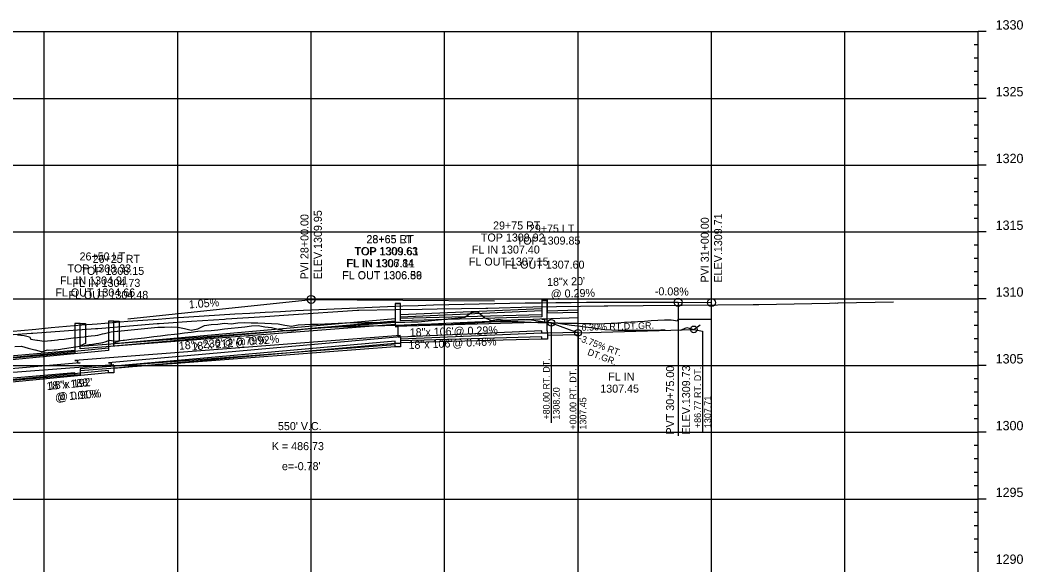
# Model space of a CAD drawing. Extents: x 670877 to 686811, y 705985 to 708501.
# Drawn here: x 686059 to 686811, y 708094 to 708501 of the extents above; entities that cross this region are included whole.
import ezdxf

# ---------------------------------------------------------------- set-up
doc = ezdxf.new("R2010")
doc.units = 0
for name, color, linetype in [('30', 7, 'Continuous'), ('37', 7, 'Continuous'), ('DRAINAGE_HGL LEFT', 7, 'Continuous'), ('DRAINAGE_HGL RIGHT', 7, 'Continuous'), ('Profile Drainage Annot Left', 7, 'Continuous'), ('Profile Drainage Annot Right', 7, 'Continuous'), ('R_Drainage Extensions_LEFT', 7, 'Continuous'), ('R_Drainage Extensions_RIGHT', 7, 'Continuous'), ('R_Drainage LEFT', 7, 'Continuous'), ('R_Drainage RIGHT', 7, 'Continuous'), ('R_Exist Surface', 7, 'Continuous'), ('R_Profile Work Left', 7, 'Continuous'), ('R_Proposed Const Limits', 7, 'Continuous'), ('R_Vert Alg', 7, 'Continuous'), ('R_Vert Alg Annot', 7, 'Continuous'), ('R_Vert Alg RT DT', 7, 'Continuous'), ('R_Vert Alg RT DT Annot', 7, 'Continuous')]:
    doc.layers.add(name, color=color, linetype=linetype)

msp = doc.modelspace()

# ---------------------------------------------------------------- linework, layer by layer
at = {"layer": '37'}
for p, q in [((684477.28, 708492.85), (686777.28, 708492.85)), ((686077.28, 707892.85), (686077.28, 708492.85)), ((686177.28, 707892.85), (686177.28, 708492.85)), ((686277.28, 707892.85), (686277.28, 708492.85)), ((686377.28, 707892.85), (686377.28, 708492.85)), ((686477.28, 707892.85), (686477.28, 708492.85)), ((686577.28, 707892.85), (686577.28, 708492.85)), ((686677.28, 707892.85), (686677.28, 708492.85)), ((686777.28, 707892.85), (686777.28, 708492.85)), ((686783.28, 708492.85), (686777.28, 708492.85)), ((686777.28, 708482.85), (686774.28, 708482.85)), ((686777.28, 708472.85), (686774.28, 708472.85)), ((686777.28, 708462.85), (686774.28, 708462.85)), ((686777.28, 708452.85), (686774.28, 708452.85)), ((684477.28, 708442.85), (686777.28, 708442.85)), ((686783.28, 708442.85), (686777.28, 708442.85)), ((686777.28, 708432.85), (686774.28, 708432.85)), ((686777.28, 708422.85), (686774.28, 708422.85)), ((686777.28, 708412.85), (686774.28, 708412.85)), ((686777.28, 708402.85), (686774.28, 708402.85)), ((684477.28, 708392.85), (686777.28, 708392.85)), ((686783.28, 708392.85), (686777.28, 708392.85)), ((686777.28, 708382.85), (686774.28, 708382.85)), ((686777.28, 708372.85), (686774.28, 708372.85)), ((686777.28, 708362.85), (686774.28, 708362.85)), ((686777.28, 708352.85), (686774.28, 708352.85)), ((684477.28, 708342.85), (686777.28, 708342.85)), ((686783.28, 708342.85), (686777.28, 708342.85)), ((686777.28, 708332.85), (686774.28, 708332.85)), ((686777.28, 708322.85), (686774.28, 708322.85)), ((686777.28, 708312.85), (686774.28, 708312.85)), ((686777.28, 708302.85), (686774.28, 708302.85)), ((684477.28, 708292.85), (686777.28, 708292.85)), ((686783.28, 708292.85), (686777.28, 708292.85)), ((686777.28, 708282.85), (686774.28, 708282.85)), ((686777.28, 708272.85), (686774.28, 708272.85)), ((686777.28, 708262.85), (686774.28, 708262.85)), ((686777.28, 708252.85), (686774.28, 708252.85)), ((684477.28, 708242.85), (686777.28, 708242.85)), ((686783.28, 708242.85), (686777.28, 708242.85)), ((686777.28, 708232.85), (686774.28, 708232.85)), ((686777.28, 708222.85), (686774.28, 708222.85)), ((686777.28, 708212.85), (686774.28, 708212.85)), ((686777.28, 708202.85), (686774.28, 708202.85)), ((684477.28, 708192.85), (686777.28, 708192.85)), ((686783.28, 708192.85), (686777.28, 708192.85)), ((686777.28, 708182.85), (686774.28, 708182.85)), ((686777.28, 708172.85), (686774.28, 708172.85)), ((686777.28, 708162.85), (686774.28, 708162.85)), ((686777.28, 708152.85), (686774.28, 708152.85)), ((684477.28, 708142.85), (686777.28, 708142.85)), ((686783.28, 708142.85), (686777.28, 708142.85)), ((686777.28, 708132.85), (686774.28, 708132.85)), ((686777.28, 708122.85), (686774.28, 708122.85)), ((686777.28, 708112.85), (686774.28, 708112.85)), ((686777.28, 708102.85), (686774.28, 708102.85))]:
    msp.add_line(p, q, dxfattribs=at)
at = {"layer": 'DRAINAGE_HGL LEFT'}
msp.add_lwpolyline([(686452.28, 708277.68), (686454.28, 708277.68), (686454.28, 708277.68), (686454.28, 708277.68), (686340.29, 708272.6), (686342.29, 708272.6), (686342.29, 708264.29), (686344.29, 708264.29), (686125.29, 708244.79), (686127.29, 708244.79), (686127.29, 708243.32), (686129.3, 708243.32), (685935.28, 708228.55), (685937.28, 708228.55), (685937.28, 708228.55), (685939.3, 708228.55), (685859.24, 708224.45), (685857.24, 708224.45), (685857.24, 708222.25), (685855.24, 708222.25), (685780.74, 708218.25), (685782.77, 708218.25)], dxfattribs=at)
at = {"layer": 'DRAINAGE_HGL RIGHT'}
msp.add_lwpolyline([(686477.28, 708278.42), (686450.04, 708277.56), (686452.28, 708277.56), (686452.28, 708275.36), (686454.28, 708275.36), (686340.29, 708272.17), (686342.29, 708272.17), (686342.29, 708265.24), (686344.29, 708265.24), (686100.28, 708246.64), (686102.28, 708246.64), (686102.28, 708244.78), (686104.28, 708244.78), (685905.28, 708227.58), (685907.28, 708227.58), (685907.28, 708225.28), (685909.33, 708225.28), (685800.25, 708213.48), (685802.28, 708213.48)], dxfattribs=at)
at = {"layer": 'R_Drainage Extensions_LEFT'}
msp.add_lwpolyline([(686129.29, 708276.15), (686133.29, 708276.15), (686133.29, 708261.15), (686129.29, 708259.48), (686129.29, 708276.15)], dxfattribs=at)
at = {"layer": 'R_Drainage Extensions_RIGHT'}
msp.add_lwpolyline([(686104.28, 708274.35), (686108.28, 708274.35), (686108.28, 708259.35), (686104.28, 708257.68), (686104.28, 708274.35)], dxfattribs=at)
at = {"layer": 'R_Drainage LEFT'}
for points in [[(686344.29, 708288.95), (686340.29, 708288.95)], [(686340.29, 708288.95), (686340.29, 708276.09)], [(686344.29, 708279.12), (686344.29, 708288.95)], [(686454.28, 708291.35), (686450.28, 708291.35)], [(686450.28, 708291.35), (686450.28, 708283.68)], [(686454.28, 708268.85), (686454.28, 708291.35)], [(686450.28, 708285.34), (686344.29, 708280.79)], [(686450.28, 708283.68), (686344.29, 708279.12)], [(686129.29, 708276.15), (686125.28, 708276.15)], [(686125.28, 708276.15), (686125.28, 708254.06)], [(686340.29, 708277.76), (686129.29, 708258.97)], [(686129.29, 708257.3), (686129.29, 708276.15)], [(686340.29, 708276.09), (686129.29, 708257.3)], [(686450.28, 708268.68), (686344.29, 708264.12)], [(686450.28, 708267.01), (686344.29, 708262.45)], [(686450.28, 708267.01), (686450.28, 708268.68)], [(686454.28, 708267.01), (686450.28, 708267.01)], [(686454.28, 708268.85), (686454.28, 708267.01)], [(686340.29, 708261.09), (686129.29, 708242.3)], [(686340.29, 708259.42), (686129.29, 708240.64)], [(686340.29, 708259.42), (686340.29, 708261.09)], [(686344.29, 708259.42), (686340.29, 708259.42)], [(686344.29, 708264.12), (686344.29, 708259.42)], [(686125.28, 708255.73), (685939.29, 708237.7)], [(686125.28, 708254.06), (685939.29, 708236.04)], [(686125.28, 708239.06), (685939.29, 708221.04)], [(686125.28, 708237.39), (685939.29, 708219.37)], [(686125.28, 708237.39), (686125.28, 708239.06)], [(686129.29, 708237.39), (686125.28, 708237.39)], [(686129.29, 708242.3), (686129.29, 708237.39)]]:
    msp.add_lwpolyline(points, dxfattribs=at)
at = {"layer": 'R_Drainage RIGHT'}
for points in [[(686344.29, 708289.15), (686340.29, 708289.15)], [(686340.29, 708289.15), (686340.29, 708273.44)], [(686344.29, 708276.38), (686344.29, 708289.15)], [(686454.39, 708292.05), (686450.16, 708292.05)], [(686450.16, 708292.05), (686450.16, 708279.24)], [(686454.39, 708281.93), (686454.39, 708292.05)], [(686450.16, 708280.9), (686344.29, 708278.05)], [(686477.28, 708284.21), (686454.39, 708283.59)], [(686477.28, 708282.55), (686454.39, 708281.93)], [(686104.28, 708274.35), (686100.28, 708274.35)], [(686100.28, 708274.35), (686100.28, 708252.3)], [(686340.29, 708275.11), (686104.28, 708257.12)], [(686104.28, 708255.45), (686104.28, 708274.35)], [(686340.29, 708273.44), (686104.28, 708255.45)], [(686450.16, 708279.24), (686344.29, 708276.38)], [(686477.28, 708267.55), (686454.39, 708266.93)], [(686454.39, 708266.93), (686454.39, 708262.57)], [(686477.28, 708265.88), (686454.39, 708265.26)], [(686340.29, 708258.44), (686104.28, 708240.45)], [(686340.29, 708256.78), (686340.29, 708258.44)], [(686450.16, 708264.24), (686344.29, 708261.38)], [(686450.16, 708262.57), (686344.29, 708259.72)], [(686344.29, 708261.38), (686344.29, 708256.78)], [(686450.16, 708262.57), (686450.16, 708264.24)], [(686454.39, 708262.57), (686450.16, 708262.57)], [(686100.28, 708253.97), (685909.3, 708237.46)], [(686100.28, 708252.3), (685909.3, 708235.8)], [(686340.29, 708256.78), (686104.28, 708238.79)], [(686344.29, 708256.78), (686340.29, 708256.78)], [(686100.28, 708237.3), (685909.3, 708220.8)], [(686100.28, 708235.64), (685909.3, 708219.13)], [(686100.28, 708235.64), (686100.28, 708237.3)], [(686104.28, 708235.64), (686100.28, 708235.64)], [(686104.28, 708240.45), (686104.28, 708235.64)]]:
    msp.add_lwpolyline(points, dxfattribs=at)
at = {"layer": 'R_Exist Surface'}
msp.add_lwpolyline([(686030.1, 708264.31), (686067.48, 708267.1), (686068.62, 708267.17), (686115.63, 708270.52), (686117.49, 708270.65), (686161.8, 708274.28), (686163.28, 708274.37), (686187.67, 708276.07), (686212.34, 708277.63), (686213.68, 708277.76), (686242.8, 708279.63), (686260.23, 708280.66), (686312.09, 708284.35), (686312.9, 708284.38), (686340.19, 708284.8), (686360.44, 708285.01), (686371.65, 708285.24), (686408.11, 708285.73), (686409.72, 708285.77), (686443.39, 708286.72), (686443.53, 708286.73), (686496.92, 708287.44), (686499.62, 708287.49), (686552.62, 708287.98), (686555.28, 708287.99), (686608.5, 708288.53), (686612.92, 708288.58), (686665.84, 708289.62), (686670.56, 708289.72), (686671.73, 708289.54), (686672.16, 708289.7), (686713.62, 708290.61)], dxfattribs=at)
at = {"layer": 'R_Profile Work Left'}
msp.add_lwpolyline([(686055.07, 708256.97), (686060.08, 708257.29), (686065.14, 708255.92), (686070.18, 708254.56), (686070.36, 708254.51), (686075.03, 708253.25), (686075.48, 708253.13), (686079.79, 708254.6), (686080.53, 708254.31), (686084.6, 708254.49), (686085.6, 708254.62), (686089.39, 708255.11), (686090.67, 708255.28), (686094.17, 708255.76), (686095.74, 708256.02), (686098.95, 708256.55), (686100.81, 708256.85), (686103.74, 708257.32), (686105.89, 708257.67), (686108.52, 708258.1), (686110.96, 708258.49), (686113.31, 708258.86), (686116.05, 708259.3), (686118.1, 708259.63), (686121.13, 708260.11), (686122.88, 708260.64), (686126.21, 708261.76), (686127.68, 708261.55), (686131.31, 708261.1), (686132.47, 708261.25), (686136.4, 708261.79), (686137.28, 708261.92), (686142.28, 708262.5), (686147.28, 708263.09), (686152.28, 708263.68), (686159.32, 708264.51), (686164.43, 708265.12), (686169.72, 708265.74), (686174.83, 708266.35), (686177.46, 708266.66), (686182.46, 708267.26), (686187.46, 708267.85), (686192.46, 708268.45), (686197.46, 708268.92), (686202.46, 708269.08), (686207.46, 708269.63), (686212.45, 708270.19), (686217.45, 708270.75), (686222.45, 708271.3), (686227.45, 708271.86), (686232.45, 708272.42), (686237.45, 708272.9), (686242.45, 708271.9), (686247.46, 708271.29), (686252.46, 708270.14), (686257.47, 708268.98), (686262.47, 708268.87), (686267.47, 708269.5), (686272.47, 708270.18), (686277.47, 708270.87), (686282.47, 708271.35), (686287.47, 708271.51), (686292.47, 708271.67), (686297.47, 708271.83), (686302.47, 708271.99), (686307.47, 708272.15), (686312.47, 708272.3), (686317.47, 708272.46), (686322.47, 708272.6), (686327.47, 708272.71), (686332.47, 708272.81), (686337.47, 708272.92), (686342.47, 708273.11), (686343.47, 708273.14), (686347.11, 708273.29), (686352.12, 708273.49), (686357.12, 708273.7), (686362.11, 708273.68), (686367.11, 708273.66), (686372.11, 708273.64), (686377.11, 708273.62), (686382.11, 708273.87), (686387.11, 708274.17), (686392.11, 708274.47), (686397.12, 708274.75), (686400.12, 708274.91), (686402.12, 708275.02), (686407.12, 708275.3), (686412.12, 708275.57), (686417.12, 708275.81), (686422.12, 708275.77), (686427.12, 708275.73), (686432.12, 708275.7), (686437.12, 708275.57), (686442.11, 708275.26), (686447.11, 708275.13), (686452.11, 708275.01), (686457.11, 708274.9), (686462.11, 708274.78), (686467.11, 708274.66), (686472.11, 708274.55), (686477.11, 708274.47), (686482.11, 708274.39), (686487.11, 708274.32), (686492.11, 708274.02), (686497.11, 708274.28), (686502.11, 708274.59), (686507.11, 708274.9), (686512.11, 708275.21), (686517.11, 708275.52), (686522.12, 708275.84), (686527.12, 708276.15), (686532.12, 708276.46), (686537.12, 708276.78), (686542.12, 708277.09), (686547.12, 708277.08), (686552.12, 708276.32), (686552.28, 708277.47), (686557.28, 708277.47), (686562.28, 708277.47), (686567.28, 708277.47), (686572.28, 708277.47), (686577.28, 708277.46)], dxfattribs=at)
at = {"layer": 'R_Proposed Const Limits'}
for points in [[(686057.28, 708265.81), (686062.28, 708265.27), (686066.3, 708264.22), (686067.28, 708262.62), (686071.76, 708261.84), (686072.28, 708261.72), (686077.21, 708260.97), (686077.28, 708260.98), (686082.28, 708261.54), (686082.67, 708261.59), (686087.28, 708262.11), (686088.14, 708262.21), (686092.28, 708262.68), (686093.61, 708262.83), (686097.28, 708263.24), (686099.08, 708263.45), (686102.28, 708263.81), (686104.55, 708264.07), (686107.28, 708264.38), (686110.03, 708264.69), (686112.28, 708264.94), (686115.51, 708265.31), (686117.28, 708265.51), (686120.99, 708266.44), (686122.28, 708266.77), (686126.47, 708267.83), (686127.28, 708268.04), (686131.95, 708268.64), (686132.28, 708268.66), (686137.28, 708269.02), (686137.43, 708269.03), (686142.28, 708269.48), (686147.28, 708269.99), (686147.31, 708269.99), (686152.28, 708270.49), (686157.28, 708271), (686162.28, 708271.44), (686167.43, 708271.63), (686172.43, 708271.76), (686177.43, 708271.53), (686182.44, 708270.51), (686187.44, 708269.31), (686192.44, 708270.19), (686197.43, 708272.8), (686202.43, 708273.55), (686207.43, 708273.87), (686212.43, 708274.53), (686217.43, 708273.96), (686222.43, 708274.85), (686227.43, 708275.12), (686232.43, 708274.9), (686237.43, 708274.68), (686242.44, 708274.46), (686247.44, 708274.24), (686252.44, 708274.02), (686257.44, 708273.13), (686262.45, 708272.2), (686267.45, 708273.21), (686272.45, 708273.44), (686277.45, 708273.68), (686282.45, 708273.91), (686287.45, 708274.14), (686292.45, 708274.38), (686297.45, 708274.61), (686302.45, 708274.84), (686307.45, 708275.07), (686312.45, 708274.89), (686317.45, 708274.97), (686322.45, 708275.04), (686327.45, 708275.1), (686332.45, 708275.16), (686337.45, 708275.23), (686342.45, 708275.29), (686343.45, 708275.3), (686347.45, 708275.35), (686352.45, 708275.42), (686357.45, 708275.58), (686362.45, 708276.06), (686367.45, 708276.57), (686372.45, 708277.08), (686377.45, 708277.59), (686382.44, 708278.1), (686387.44, 708278.61), (686392.44, 708279.12), (686397.43, 708282.41), (686400.43, 708282.91), (686402.43, 708282.77), (686407.45, 708278.48), (686412.45, 708276.52), (686417.45, 708277.56), (686422.45, 708276.86), (686427.45, 708277.1), (686432.45, 708277.33), (686437.45, 708277.28), (686442.45, 708277.12), (686447.46, 708276.27), (686452.46, 708275.42), (686457.46, 708274.95), (686462.46, 708274.43), (686467.47, 708273.79), (686472.47, 708273.14), (686477.47, 708272.49), (686482.47, 708271.84), (686487.48, 708271.19), (686492.48, 708270.55), (686497.48, 708269.82), (686502.48, 708269.43), (686507.48, 708269.42), (686512.48, 708269.4), (686517.48, 708269.39), (686522.48, 708269.37), (686527.48, 708269.35), (686532.48, 708269.34), (686537.48, 708269.32), (686542.48, 708269.31), (686539.29, 708269.33)], [(686554.03, 708269.38), (686558.87, 708271.21), (686564.05, 708269.91), (686568.72, 708273.34)]]:
    msp.add_lwpolyline(points, dxfattribs=at)
at = {"layer": 'R_Vert Alg'}
for p, q in [((686139.78, 708277.89), (686277.28, 708292.35)), ((686277.28, 708292.35), (686414.78, 708291.25)), ((686552.28, 708290.15), (686577.28, 708289.95))]:
    msp.add_line(p, q, dxfattribs=at)
msp.add_lwpolyline([(686048.11, 708268.03), (686059.57, 708269.12), (686071.03, 708270.17), (686082.49, 708271.2), (686093.94, 708272.2), (686105.4, 708273.18), (686116.86, 708274.13), (686128.32, 708275.05), (686139.78, 708275.94), (686151.24, 708276.81), (686162.69, 708277.65), (686174.15, 708278.46), (686185.61, 708279.25), (686197.07, 708280.01), (686208.53, 708280.74), (686219.99, 708281.45), (686231.44, 708282.13), (686242.9, 708282.78), (686254.36, 708283.4), (686265.82, 708284), (686288.74, 708285.11), (686300.19, 708285.63), (686311.65, 708286.12), (686323.11, 708286.58), (686334.57, 708287.01), (686346.03, 708287.42), (686357.49, 708287.8), (686368.94, 708288.16), (686380.4, 708288.48), (686391.86, 708288.78), (686403.32, 708289.06), (686414.78, 708289.3), (686426.24, 708289.52), (686437.69, 708289.71), (686449.15, 708289.88), (686460.61, 708290.02), (686472.07, 708290.13), (686483.53, 708290.21), (686494.99, 708290.27), (686506.44, 708290.3), (686517.9, 708290.3), (686529.36, 708290.28), (686540.82, 708290.23), (686552.28, 708290.15)], dxfattribs=at)
for centre in [(686277.28, 708292.35), (686552.28, 708290.15), (686577.28, 708289.95)]:
    msp.add_circle(centre, 3, dxfattribs=at)
at = {"layer": 'R_Vert Alg Annot'}
for p, q in [((686277.28, 708292.35), (686277.28, 708382.35)), ((686577.28, 708289.95), (686577.28, 708379.95)), ((686552.28, 708290.15), (686552.28, 708190.15))]:
    msp.add_line(p, q, dxfattribs=at)
at = {"layer": 'R_Vert Alg RT DT'}
for p, q in [((686457.28, 708274.85), (686477.28, 708267.35)), ((686477.28, 708267.35), (686564.04, 708269.91))]:
    msp.add_line(p, q, dxfattribs=at)
for centre in [(686457.28, 708274.85), (686564.04, 708269.91), (686477.28, 708267.35)]:
    msp.add_circle(centre, 2.5, dxfattribs=at)
at = {"layer": 'R_Vert Alg RT DT Annot'}
for p, q in [((686457.28, 708274.85), (686457.28, 708199.85)), ((686477.28, 708267.35), (686477.28, 708192.35))]:
    msp.add_line(p, q, dxfattribs=at)
msp.add_lwpolyline([(686564.04, 708269.91), (686570.7, 708268.51), (686570.7, 708193.51)], dxfattribs=at)

# ---------------------------------------------------------------- texts
at = {"layer": '30'}
for s, p in [('1330', (686790.28, 708494.35)), ('1325', (686790.28, 708444.35)), ('1320', (686790.28, 708394.35)), ('1315', (686790.28, 708344.35)), ('1310', (686790.28, 708294.35)), ('1305', (686790.28, 708244.35)), ('1300', (686790.28, 708194.35)), ('1295', (686790.28, 708144.35)), ('1290', (686790.28, 708094.35))]:
    msp.add_text(s, height=7, dxfattribs=at).set_placement(p)
at = {"layer": 'Profile Drainage Annot Left'}
for s, p in [('29+75 LT', (686440.45, 708342.36)), ('28+65 LT', (686318.71, 708334.31)), ('TOP 1309.85', (686431.34, 708333.36)), ('26+50 LT', (686103.71, 708321.51)), ('TOP 1309.61', (686310.04, 708325.31)), ('TOP 1308.33', (686094.6, 708312.51)), ('FL IN 1307.11', (686304.04, 708316.31)), ('FL OUT 1307.60', (686422.38, 708315.36)), ('FL OUT 1306.86', (686300.6, 708307.31)), ('FL IN 1304.91', (686089.04, 708303.51)), ('FL OUT 1304.66', (686085.6, 708294.51)), ('FL IN ', (686499.91, 708231.53)), ('1307.45', (686493.97, 708222.53))]:
    msp.add_text(s, height=6, dxfattribs=at).set_placement(p)
for s, rotation, p in [('18"x 212\'@ 0.92%', 5.08825, (686187.78, 708254.03)), ('18"x 106\'@ 0.46%', 2.46144, (686350.33, 708255.08)), ('18"x 188\'', 5.53462, (686079.17, 708224.33)), ('@ 1.01%', 5.53462, (686085.56, 708215.91))]:
    msp.add_text(s, height=6, rotation=rotation, dxfattribs=at).set_placement(p)
at = {"layer": 'Profile Drainage Annot Right'}
for s, p in [('29+75 RT', (686413.61, 708344.67)), ('28+65 RT', (686318.71, 708334.51)), ('TOP 1309.92', (686404.49, 708335.67)), (' FL IN 1307.40', (686395.53, 708326.67)), ('26+25 RT', (686113.5, 708319.71)), ('TOP 1309.63', (686309.6, 708325.51)), ('FL IN 1306.84', (686303.6, 708316.51)), ('FL OUT 1307.15', (686395.49, 708317.67)), ('TOP 1308.15', (686104.39, 708310.71)), ('FL OUT 1306.59', (686300.57, 708307.51)), ('FL IN 1304.73', (686098.39, 708301.71)), ('FL OUT 1304.48', (686095.4, 708292.71))]:
    msp.add_text(s, height=6, dxfattribs=at).set_placement(p)
for s, rotation, p in [('18"x 20\'', 1.55782, (686454.16, 708302.37)), ('@ 0.29%', 1.55782, (686456.95, 708293.45)), ('18"x 236\'@ 0.79%', 4.20867, (686178.29, 708254.58)), ('18"x 106\'@ 0.29%', 1.55782, (686351.23, 708264.6)), ('18"x 192\'', 4.93996, (686080.84, 708224.72)), ('@ 0.90%', 4.93996, (686087.15, 708216.23))]:
    msp.add_text(s, height=6, rotation=rotation, dxfattribs=at).set_placement(p)
at = {"layer": 'R_Vert Alg Annot'}
for s, rotation, p in [('PVI 28+00.00', 90, (686275.28, 708307.35)), ('ELEV.1309.95', 90, (686285.28, 708307.35)), ('ELEV.1309.71', 90, (686585.28, 708304.95)), ('PVI 31+00.00', 90, (686575.28, 708304.95)), ('-0.08%', 359.54164, (686534.83, 708295.41)), ('1.05%', 4.1542, (686185.79, 708285.55)), ('PVT 30+75.00', 90, (686549.28, 708191.15)), ('ELEV.1309.73', 90, (686561.28, 708191.15))]:
    msp.add_text(s, height=6, rotation=rotation, dxfattribs=at).set_placement(p)
for s, p in [("550' V.C.", (686252.38, 708194.48)), ('K = 486.73', (686247.81, 708179.48)), ("e=-0.78'", (686255.38, 708164.48))]:
    msp.add_text(s, height=6, dxfattribs=at).set_placement(p)
at = {"layer": 'R_Vert Alg RT DT Annot'}
for s, rotation, p in [('0.30% RT.DT.GR.', 1.68994, (686480.04, 708268.82)), ('-3.75% RT.', 339.44395, (686477.18, 708261.46)), ('DT.GR.', 339.44395, (686483.91, 708250.93)), ('+80.00 RT. DT.', 90, (686456.03, 708202.35)), ('+00.00 RT. DT.', 90, (686476.03, 708194.85)), ('+86.77 RT. DT.', 90, (686569.45, 708196.01)), ('1308.20', 90, (686463.53, 708202.35)), ('1307.71', 90, (686576.95, 708196.01)), ('1307.45', 90, (686483.53, 708194.85))]:
    msp.add_text(s, height=5, rotation=rotation, dxfattribs=at).set_placement(p)

doc.saveas('drawing.dxf')
